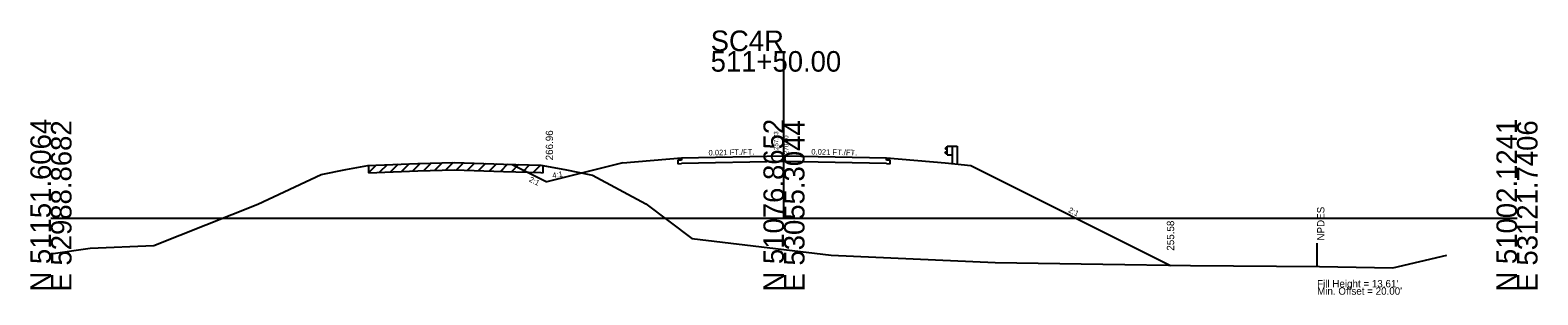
# Model space of a CAD drawing. Extents: x 7498 to 13027, y 90095 to 109625.
# Drawn here: x 8521.2 to 8726.8, y 101594.7 to 101630.8 of the extents above; entities that cross this region are included whole.
import ezdxf

# ---------------------------------------------------------------- set-up
doc = ezdxf.new("R2010")
doc.units = 0
for name, color, linetype in [('Level 10', 7, 'Continuous'), ('Level 11', 7, 'Continuous'), ('Level 12', 7, 'Continuous'), ('Level 24', 7, 'Continuous'), ('Level 32', 7, 'Continuous'), ('Level 33', 7, 'Continuous'), ('Level 50', 7, 'Continuous'), ('Level 55', 7, 'Continuous'), ('Level 59', 7, 'Continuous'), ('Level 6', 7, 'Continuous'), ('Level 60', 7, 'Continuous'), ('Level 61', 7, 'Continuous'), ('Level 63', 7, 'Continuous'), ('Level 7', 7, 'Continuous')]:
    doc.layers.add(name, color=color, linetype=linetype)

msp = doc.modelspace()

# ---------------------------------------------------------------- linework, layer by layer
at = {"layer": 'Level 11'}
for p, q in [((8609.99, 101613.07), (8609.49, 101613.05)), ((8609.49, 101613.05), (8609.49, 101612.57)), ((8609.99, 101613.37), (8609.99, 101613.07)), ((8637.99, 101613.07), (8637.99, 101613.37)), ((8638.49, 101613.05), (8637.99, 101613.07)), ((8638.49, 101612.57), (8638.49, 101613.05)), ((8609.49, 101612.57), (8609.99, 101612.59)), ((8637.99, 101612.59), (8638.49, 101612.57))]:
    msp.add_line(p, q, dxfattribs=at)
at = {"layer": 'Level 12'}
for p, q in [((8623.99, 101612.88), (8609.99, 101612.59)), ((8637.99, 101612.59), (8623.99, 101612.88))]:
    msp.add_line(p, q, dxfattribs=at)
at = {"layer": 'Level 24'}
for p, q in [((8646.26, 101613.78), (8646.26, 101614.95)), ((8646.26, 101614.95), (8646.93, 101614.95)), ((8646.93, 101614.95), (8646.93, 101612.6)), ((8646.93, 101614.95), (8647.6, 101614.95)), ((8647.6, 101614.95), (8647.6, 101612.54)), ((8646.26, 101614.88), (8645.99, 101614.68)), ((8645.99, 101614.68), (8645.99, 101614.63)), ((8645.99, 101614.63), (8646.26, 101614.43)), ((8645.99, 101614.1), (8646.26, 101614.3)), ((8645.99, 101614.05), (8645.99, 101614.1)), ((8646.26, 101613.85), (8645.99, 101614.05)), ((8646.26, 101613.78), (8646.93, 101613.78))]:
    msp.add_line(p, q, dxfattribs=at)
at = {"layer": 'Level 55'}
msp.add_line((8696.72, 101598.73), (8696.72, 101601.73), dxfattribs=at)
at = {"layer": 'Level 59'}
for p, q in [((8609.99, 101613.37), (8623.99, 101613.66)), ((8623.99, 101613.66), (8637.99, 101613.37))]:
    msp.add_line(p, q, dxfattribs=at)
at = {"layer": 'Level 6'}
for p, q in [((8601.99, 101612.7), (8609.99, 101613.37)), ((8637.99, 101613.37), (8645.99, 101612.7)), ((8645.99, 101612.7), (8649.49, 101612.35))]:
    msp.add_line(p, q, dxfattribs=at)
at = {"layer": 'Level 60'}
for p, q in [((8552.19, 101607.05), (8560.86, 101611.09)), ((8560.86, 101611.09), (8564.2, 101611.8)), ((8564.2, 101611.8), (8567.24, 101612.35)), ((8567.24, 101612.35), (8574.06, 101612.59)), ((8574.06, 101612.59), (8579.05, 101612.74)), ((8579.05, 101612.74), (8585.73, 101612.51)), ((8585.73, 101612.51), (8590.8, 101612.38)), ((8590.8, 101612.38), (8594.1, 101611.78)), ((8594.1, 101611.78), (8597.89, 101611.02)), ((8597.89, 101611.02), (8605.16, 101607.12)), ((8538.03, 101601.45), (8552.19, 101607.05)), ((8605.16, 101607.12), (8611.43, 101602.37)), ((8523.99, 101600.31), (8529.33, 101601.06)), ((8529.33, 101601.06), (8538.03, 101601.45)), ((8611.43, 101602.37), (8623.99, 101600.88)), ((8623.99, 101600.88), (8630.45, 101600.12)), ((8630.45, 101600.12), (8652.78, 101599.12)), ((8652.78, 101599.12), (8667.51, 101598.89)), ((8667.51, 101598.89), (8679.45, 101598.69)), ((8679.45, 101598.69), (8697.06, 101598.57)), ((8697.06, 101598.57), (8707.07, 101598.37)), ((8707.07, 101598.37), (8714.41, 101600.1))]:
    msp.add_line(p, q, dxfattribs=at)
at = {"layer": 'Level 61'}
for p, q in [((8568.35, 101612.39), (8567.31, 101611.35)), ((8567.31, 101612.35), (8567.31, 101611.35)), ((8567.31, 101611.35), (8574.06, 101611.59)), ((8569.85, 101612.44), (8568.81, 101611.4)), ((8571.35, 101612.49), (8570.31, 101611.46)), ((8572.85, 101612.55), (8571.81, 101611.51)), ((8574.35, 101612.6), (8573.31, 101611.57)), ((8574.06, 101611.59), (8579.05, 101611.74)), ((8575.85, 101612.65), (8574.81, 101611.61)), ((8577.35, 101612.69), (8576.31, 101611.66)), ((8578.85, 101612.74), (8577.81, 101611.7)), ((8579.05, 101611.74), (8585.73, 101611.51)), ((8580.28, 101612.7), (8579.31, 101611.73)), ((8581.78, 101612.65), (8580.81, 101611.68)), ((8583.28, 101612.6), (8582.31, 101611.63)), ((8584.78, 101612.55), (8583.81, 101611.58)), ((8586.29, 101612.5), (8585.31, 101611.53)), ((8585.73, 101611.51), (8590.8, 101611.38)), ((8587.79, 101612.46), (8586.81, 101611.48)), ((8589.29, 101612.42), (8588.31, 101611.44)), ((8590.79, 101612.38), (8589.81, 101611.4)), ((8590.8, 101611.38), (8591.15, 101611.31)), ((8591.15, 101611.31), (8591.15, 101612.31))]:
    msp.add_line(p, q, dxfattribs=at)
at = {"layer": 'Level 63'}
for p, q in [((8623.99, 101605.16), (8623.99, 101627.91)), ((8523.99, 101605.16), (8623.99, 101605.16)), ((8623.99, 101605.16), (8723.99, 101605.16))]:
    msp.add_line(p, q, dxfattribs=at)
at = {"layer": 'Level 7'}
for p, q in [((8586.91, 101612.48), (8591.65, 101610.11)), ((8601.99, 101612.7), (8591.65, 101610.11)), ((8649.49, 101612.35), (8676.72, 101598.73))]:
    msp.add_line(p, q, dxfattribs=at)

# ---------------------------------------------------------------- texts
at = {"layer": 'Level 10'}
msp.add_text('257.73', height=0.6, rotation=90, dxfattribs=at).set_placement((8623.21, 101614.45))
at = {"layer": 'Level 32'}
for s, rotation, p in [('0.021 FT./FT.', 1.1916, (8613.7, 101613.69)), ('0.021 FT./FT.', 358.8084, (8627.71, 101613.83)), ('2:1', 333.435, (8589.13, 101610.19)), ('4:1', 9.4623, (8592.45, 101610.59)), ('2:1', 333.435, (8662.71, 101606.02))]:
    msp.add_text(s, height=0.75, rotation=rotation, dxfattribs=at).set_placement(p)
at = {"layer": 'Level 33'}
for s, p in [('266.96', (8592.49, 101613.03)), ('255.58', (8677.22, 101600.73))]:
    msp.add_text(s, height=1, rotation=90, dxfattribs=at).set_placement(p)
at = {"layer": 'Level 50'}
msp.add_text(' NPDES', height=1, rotation=90, dxfattribs=at).set_placement((8697.72, 101601.73))
for s, p in [("Fill Height = 13.61' ", (8696.72, 101595.73)), ("Min. Offset = 20.00' ", (8696.72, 101594.73))]:
    msp.add_text(s, height=1, dxfattribs=at).set_placement(p)
at = {"layer": 'Level 59'}
msp.add_text(' 270.50', height=0.6, rotation=90, dxfattribs=at).set_placement((8624.59, 101613.66))
at = {"layer": 'Level 63'}
for s, p in [('SC4R', (8613.99, 101627.91)), ('511+50.00', (8613.99, 101625.11))]:
    msp.add_text(s, height=2.8, dxfattribs=at).set_placement(p)
for s, p in [('N 51151.6064', (8523.99, 101595.16)), ('E 52988.8682', (8526.79, 101595.16)), ('N 51076.8652', (8623.99, 101595.16)), ('E 53055.3044', (8626.79, 101595.16)), ('N 51002.1241', (8723.99, 101595.16)), ('E 53121.7406', (8726.79, 101595.16))]:
    msp.add_text(s, height=2.8, rotation=90, dxfattribs=at).set_placement(p)

doc.saveas('drawing.dxf')
